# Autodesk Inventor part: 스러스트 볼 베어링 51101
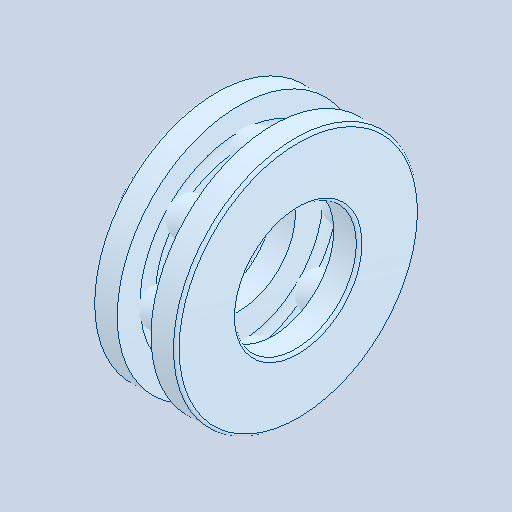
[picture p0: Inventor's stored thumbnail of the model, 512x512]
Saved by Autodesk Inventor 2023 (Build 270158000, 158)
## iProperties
Created: 2024-07
Part Number: 스러스트 볼 베어링 51101
Material: 강철, 연강
Description: 롤링 베어링 - 플랫 뒷면이 있는 스러스트 볼 베어링
Document SubType Name: Modeling
Designer: home
Density: 7.85 g/cm^3
Appearance: 기본값
Author: jhkim
Sending System: Autodesk Inventor 2025
Preprocessor: ST-DEVELOPER v20
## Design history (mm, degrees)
feature "Solid1"
feature "Solid1:1"
feature "Solid1:2"
feature "Solid1:3"
feature "Solid1:4"
feature "Solid1:5"
feature "Solid1:6"
feature "Solid1:7"
feature "Solid1:8"
feature "Solid1:9"
node "솔리드1"
node "솔리드2"
node "솔리드3"
node "솔리드4"
node "솔리드5"
node "솔리드6"
node "솔리드7"
node "솔리드8"
node "솔리드9"
node "솔리드10"
